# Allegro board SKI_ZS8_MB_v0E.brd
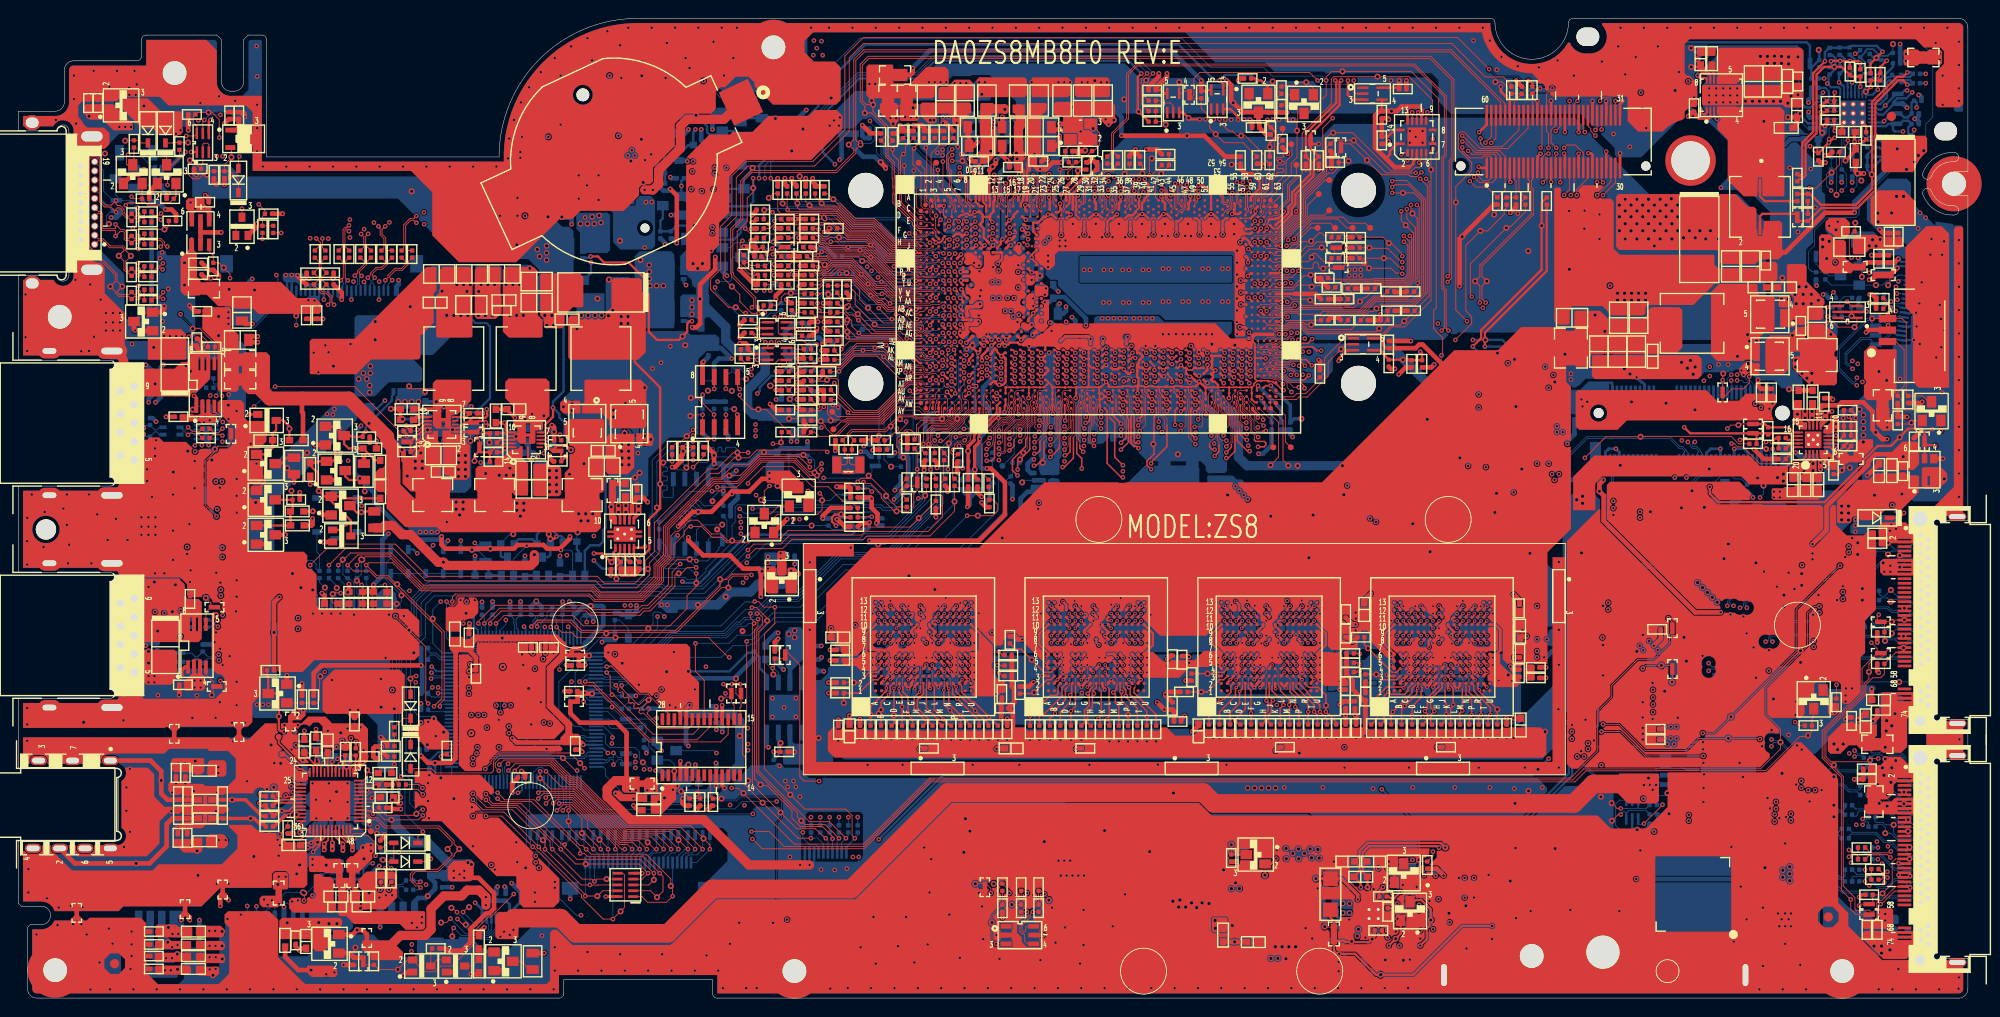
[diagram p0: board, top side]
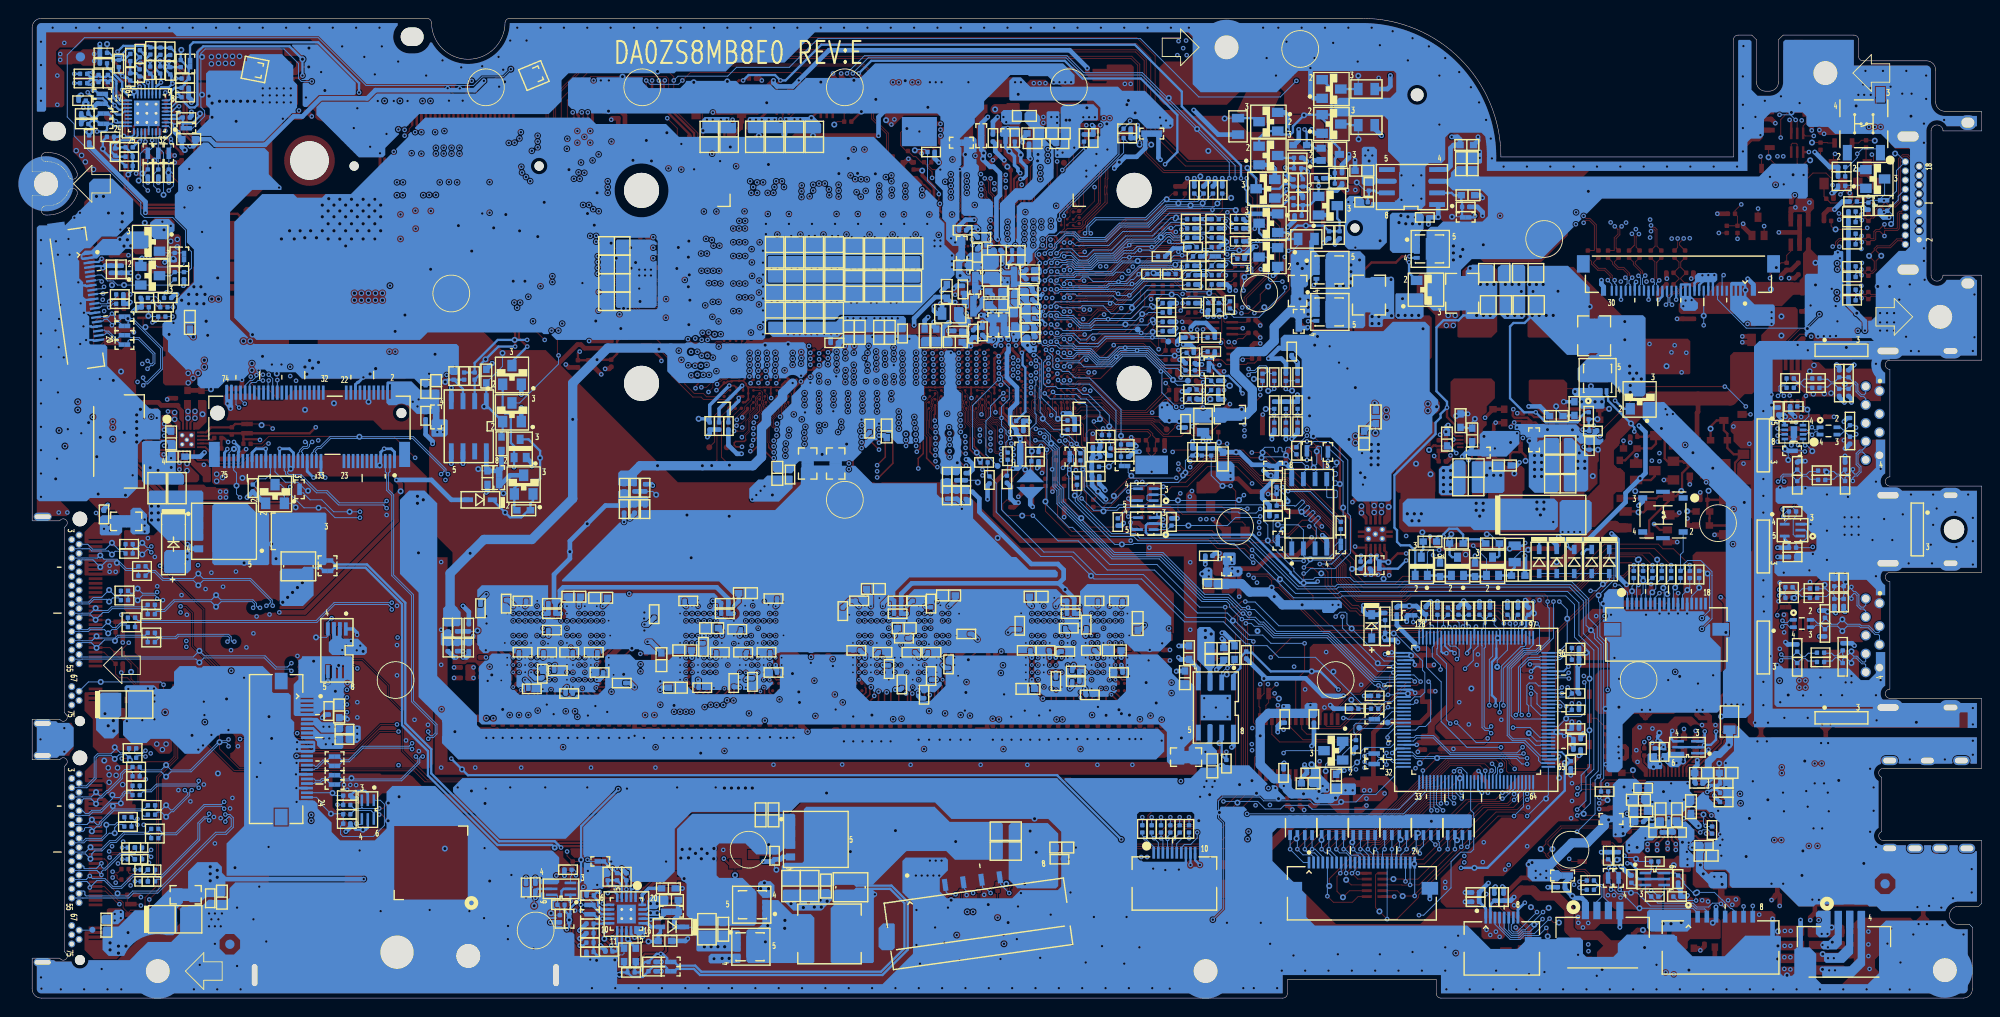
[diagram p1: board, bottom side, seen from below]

Outline 212.1 x 106.62 mm; copper layers: TOP, SGND, IN1, IN2, SVCC, IN3, SGND1, BOTTOM. Coordinates in mm from the lower left corner of the outline.
Outline path: 0,96.41 0,94.37 4.2,94.37 arc(4.85,95.02) 5.5,94.37 5.5,78.67 arc(4.85,78.02) 4.2,78.67 0,78.67 0,69.42 9.98,69.42 arc(10.48,68.92) 9.98,68.42 9.98,56.72 arc(10.48,56.22) 9.98,55.72 0,55.72 0,46.32 9.98,46.32 arc(10.48,45.82) 9.98,45.32 9.98,33.62 arc(10.48,33.12) 9.98,32.62 0,32.62 0,25 10.7,25 arc(11.19,24.6) 10.9,24.04 10.9,18.11 arc(11.19,17.55) 10.7,17.15 0,17.15 0,10.3 0.3,10 2.5,10 arc(3.5,9) 2.5,8 1.3,8 1,7.7 1,1 arc(1.29,0.29) 2,0 58.83,0 arc(59.18,0.15) 59.33,0.5 59.33,2 75.53,2 75.53,0.5 arc(75.68,0.15) 76.03,0 211.1,0 arc(211.81,0.29) 212.1,1 212.1,4.34 209.09,4.34 arc(208.42,4.23) 208.44,4.91 208.59,5.08 208.59,25.21 208.44,25.38 arc(208.43,26.05) 209.09,25.94 212.1,25.94 212.1,30.34 209.09,30.34 arc(208.42,30.23) 208.44,30.91 208.59,31.08 208.59,51.21 208.44,51.38 arc(208.42,52.05) 209.09,51.94 212.1,51.94 212.1,87.32 210.6,87.32 arc(209.3,88.62) 210.6,89.92 212.1,89.92 212.1,105.62 arc(211.81,106.33) 211.1,106.62 169.15,106.62 arc(168.8,106.48) 168.65,106.13 arc(164.65,102.17) 160.65,106.13 arc(160.5,106.48) 160.15,106.62 67.38,106.62 arc(56.72,102.2) 52.3,91.54 27,91.54 27,104.3 arc(26.85,104.65) 26.5,104.8 25,104.8 24.5,104.3 24.5,99.7 arc(24.21,98.99) 23.5,98.7 23.1,98.7 arc(22.39,98.99) 22.1,99.7 22.1,104.3 21.6,104.8 13.89,104.8 arc(13.54,104.65) 13.39,104.3 13.39,102.5 arc(13.25,102.15) 12.89,102 6,102 arc(5.29,101.71) 5,101 5,97.51 arc(4.71,96.8) 4,96.51 0.01,96.51 arc(0,96.46) 0,96.41 ; 207.21,89.79 arc(208.45,91.41) 210.4,92.02 210.6,92.02 arc(211.1,91.52) 210.6,91.02 210.4,91.02 arc(209.03,90.59) 208.15,89.45 arc(207.51,89.15) 207.21,89.79 ; 207.21,87.45 arc(207.51,88.09) 208.15,87.79 arc(209.03,86.65) 210.4,86.22 210.6,86.22 arc(211.1,85.72) 210.6,85.22 210.4,85.22 arc(208.45,85.83) 207.21,87.45

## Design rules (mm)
constraint set DEFAULT: min track width 0.102
net group W30-T123B: nets +3V3_ADO +5V_ADO_AVDD
net group W50-T123B: nets +5V_ADO_PVDD1 +5V_ADO_PVDD2
net group DFP-S4(4: nets CN_HDMI_CLKN CN_HDMI_CLKP CN_HDMI_TXN0 CN_HDMI_TXN1 CN_HDMI_TXN2 CN_HDMI_TXP0 CN_HDMI_TXP1 CN_HDMI_TXP2 EDP_AUXN EDP_AUXN_C EDP_AUXP EDP_AUXP_C EDP_TXN0 EDP_TXN0_C EDP_TXN1_C EDP_TXN2 EDP_TXN2_C EDP_TXN3 EDP_TXN3_C EDP_TXP0 EDP_TXP0_C EDP_TXP1_C EDP_TXP2 EDP_TXP2_C EDP_TXP3 EDP_TXP3_C HDMI_CLKN HDMI_CLKP HDMI_TXN0 HDMI_TXN1 HDMI_TXN2 HDMI_TXP0 HDMI_TXP1 HDMI_TXP2 PEG_RXN4 PEG_RXN5_L0 PEG_RXN5_L1 PEG_RXN5_L2 PEG_RXN5_L3 PEG_RXN6_L1 PEG_RXN6_L1_N PEG_RXN6_L2_N PEG_RXN6_L3 PEG_RXP4 PEG_RXP5_L0 PEG_RXP5_L1 PEG_RXP5_L2 PEG_RXP5_L3 PEG_RXP6_L1 PEG_RXP6_L1_N PEG_RXP6_L2_N PEG_RXP6_L3 PEG_TXN4 PEG_TXN5_L0 PEG_TXN5_L1 PEG_TXN5_L2 PEG_TXN5_L3 PEG_TXN6_L1 PEG_TXN6_L2_N PEG_TXN6_L3 PEG_TXP4 PEG_TXP5_L0 PEG_TXP5_L1 PEG_TXP5_L2 PEG_TXP5_L3 PEG_TXP6_L1 PEG_TXP6_L2_N PEG_TXP6_L3 R_PEG_TXN4 R_PEG_TXP4 SATA_RXN1/PEG_RXN6_L2 SATA_RXN3/PEG_RXN6_L0 SATA_RXP1/PEG_RXP6_L2 SATA_RXP3/PEG_RXP6_L0 SATA_TXN1/PEG_TXN6_L2 SATA_TXN3/PEG_TXN6_L0 SATA_TXP1/PEG_TXP6_L2 SATA_TXP3/PEG_TXP6_L0 USB2N0_R USB2N1 USB2N4 USB2N7 USB2P0_R USB2P1 USB2P4 USB2P7 USB3_RXN1 USB3_RXN1_USB3 USB3_RXN2 USB3_RXN2_USB3 USB3_RXP1 USB3_RXP1_USB3 USB3_RXP2 USB3_RXP2_USB3 USB3_TXN1 USB3_TXN1_R USB3_TXN1_USB3 USB3_TXN2 USB3_TXN2_R USB3_TXN2_USB3 USB3_TXP1 USB3_TXP1_R USB3_TXP1_USB3 USB3_TXP2 USB3_TXP2_R USB3_TXP2_USB3
net group DFP-S4W4-TB: nets PEG_RXN5_L1_N PEG_RXN5_L2_N PEG_RXN5_L3_N PEG_RXN6_L3_N PEG_RXP5_L1_N PEG_RXP5_L2_N PEG_RXP5_L3_N PEG_RXP6_L3_N PEG_TXN5_L1_N PEG_TXN5_L2_N PEG_TXN5_L3_N PEG_TXN6_L1_N PEG_TXN6_L3_N PEG_TXP5_L1_N PEG_TXP5_L2_N PEG_TXP5_L3_N PEG_TXP6_L1_N PEG_TXP6_L3_N SATA_RXN3/PEG_RXN6_L0_N SATA_RXP3/PEG_RXP6_L0_N SATA_TXN3/PEG_TXN6_L0_N SATA_TXP3/PEG_TXP6_L0_N USB2N3_C USB2N6_C USB2N7_C USB2P3_C USB2P6_C USB2P7_C
net group DFP-S5(5: nets CLK_PCIE_NGFF0_N CLK_PCIE_NGFF0_P CLK_PCIE_NGFF1_N CLK_PCIE_NGFF1_P CLK_PCIE_WLAN_N CLK_PCIE_WLAN_P CLK_PCIE_XDPN CLK_PCIE_XDPP
net group DFP-S5W4(4.5: nets 2ND_MBCLK 2ND_MBDATA CLK_SCLK CLK_SDATA DMIC_CLK DMIC_CLK_C DMIC_DATA DMIC_DATA_C HDMI_DDCCLK HDMI_DDCDAT MBCLK MBDATA PCH_I2C1_CLK PCH_I2C1_DAT SENSOR_PCH_CLK SENSOR_PCH_DAT SENSOR_SCL SENSOR_SDA SMB_ME1_CLK SMB_ME1_DAT SMB_PCH_CLK SMB_PCH_DAT TPCLK TPDATA
net group DFP-S5W4-TB: nets RTC_X1 RTC_X2 XTAL24_IN XTAL24_OUT
net group DFP-S7(5)W6.5(6)-T3: nets MA_CLKN0 MA_CLKN1 MA_CLKP0 MA_CLKP1 MA_DQSN1 MA_DQSN3 MA_DQSN5 MA_DQSN6 MA_DQSP1 MA_DQSP3 MA_DQSP5 MA_DQSP6 MB_CLKN0 MB_CLKN1 MB_CLKP0 MB_CLKP1 MB_DQSN1 MB_DQSN3 MB_DQSN5 MB_DQSN7 MB_DQSP1 MB_DQSP3 MB_DQSP5 MB_DQSP7
net group DFP-S7(7)W6.5(7.5)-T1: nets MB_DQSN0 MB_DQSN2 MB_DQSN4 MB_DQSN6 MB_DQSP0 MB_DQSP2 MB_DQSP4 MB_DQSP6
net group DFP-S7(7)W6.5(7.5)-T2: nets MA_DQSN0 MA_DQSN2 MA_DQSN4 MA_DQSN7 MA_DQSP0 MA_DQSP2 MA_DQSP4 MA_DQSP7
net group DFP-S15W40-T13B: nets L_SPK+ L_SPK- R_SPK+ R_SPK- SPK_L+ SPK_L- SPK_R+ SPK_R-
net group W4(4.5: nets 51624_ALERT# 51624_CLK 51624_DATA APWROK_R CLK_PCH_PCI3 CLK_PCH_PCI4 CLK_PCI_EC CLK_PCI_LPC CLK_PCI_LPC_C CLK_PCI_TPM DDR_PG_CTRL DNBSWON# DPWROK DPWROK_R DSWVREN EC_PWROK EC_PWROK_R H_CPU_SVIDART# H_CPU_SVIDCLK H_CPU_SVIDDAT H_PECI H_PROCHOT# H_PROCHOT#_R HDA_BCLK_R HDA_RST#_R HDA_SDO_R HDA_SYNC_R LPC_LAD0 LPC_LAD0_C LPC_LAD1 LPC_LAD1_C LPC_LAD2 LPC_LAD2_C LPC_LAD3 LPC_LAD3_C LPC_LFRAME# LPC_LFRAME#_C PCH_AZ_CODEC_BITCLK PCH_AZ_CODEC_RST# PCH_AZ_CODEC_SDIN0 PCH_AZ_CODEC_SDOUT PCH_AZ_CODEC_SYNC PCH_INTVRMEN PCH_PWRBTN# PCH_RSMRST# PCH_SPI_CLK PCH_SPI_CLK_EC PCH_SPI_CLK_R PCH_SPI_CS0# PCH_SPI_IO2 PCH_SPI_IO3 PCH_SPI_SI PCH_SPI_SI_EC PCH_SPI_SI_R PCH_SPI_SO PCH_SPI_SO_EC PCH_SPI_SO_R PCI_PLTRST# RSMRST# RTC_RST# SIO_EXT_SCI# SIO_EXT_SMI# SIO_RCIN# SM_INTRUDER# SPI_CS0#_UR_ME SPI_HOLD_IO3_ME SPI_WP_IO2_ME SRTC_RST# SYS_PWROK SYS_PWROK_R SYS_RESET# SYS_SHDN# THRMTRIP# VCCST_PWRGD VCCST_PWRGD_R VR_SVID_ALERT# VR_SVID_CLK VR_SVID_DATA XDP_BPM#0 XDP_BPM#1
net group W6.5(6)-T3: nets MA_DQ8 MA_DQ9 MA_DQ10 MA_DQ11 MA_DQ12 MA_DQ13 MA_DQ14 MA_DQ15 MA_DQ24 MA_DQ25 MA_DQ26 MA_DQ27 MA_DQ28 MA_DQ29 MA_DQ30 MA_DQ31 MA_DQ40 MA_DQ41 MA_DQ42 MA_DQ43 MA_DQ44 MA_DQ45 MA_DQ46 MA_DQ47 MA_DQ48 MA_DQ49 MA_DQ50 MA_DQ51 MA_DQ52 MA_DQ53 MA_DQ54 MA_DQ55 MB_DQ8 MB_DQ9 MB_DQ10 MB_DQ11 MB_DQ12 MB_DQ13 MB_DQ14 MB_DQ15 MB_DQ24 MB_DQ25 MB_DQ26 MB_DQ27 MB_DQ28 MB_DQ29 MB_DQ30 MB_DQ31 MB_DQ40 MB_DQ41 MB_DQ42 MB_DQ43 MB_DQ44 MB_DQ45 MB_DQ46 MB_DQ47 MB_DQ56 MB_DQ57 MB_DQ58 MB_DQ59 MB_DQ60 MB_DQ61 MB_DQ62 MB_DQ63
net group W6.5(7.5)-T1: nets MA_AMA0 MA_AMA1 MA_AMA2 MA_AMA3 MA_AMA4 MA_AMA5 MA_AMA6 MA_AMA7 MA_AMA8 MA_AMA9 MA_BMA0 MA_BMA1 MA_BMA2 MA_BMA3 MA_BMA4 MA_BMA5 MA_BMA6 MA_BMA7 MA_BMA8 MA_BMA9 MA_CKE0 MA_CKE1 MA_CKE2 MA_CKE3 MB_DQ0 MB_DQ1 MB_DQ2 MB_DQ3 MB_DQ4 MB_DQ5 MB_DQ6 MB_DQ7 MB_DQ16 MB_DQ17 MB_DQ18 MB_DQ19 MB_DQ20 MB_DQ21 MB_DQ22 MB_DQ23 MB_DQ32 MB_DQ33 MB_DQ34 MB_DQ35 MB_DQ36 MB_DQ37 MB_DQ38 MB_DQ39 MB_DQ48 MB_DQ49 MB_DQ50 MB_DQ51 MB_DQ52 MB_DQ53 MB_DQ54 MB_DQ55
net group W6.5(7.5)-T2: nets MA_DQ0 MA_DQ1 MA_DQ2 MA_DQ3 MA_DQ4 MA_DQ5 MA_DQ6 MA_DQ7 MA_DQ16 MA_DQ17 MA_DQ18 MA_DQ19 MA_DQ20 MA_DQ21 MA_DQ22 MA_DQ23 MA_DQ32 MA_DQ33 MA_DQ34 MA_DQ35 MA_DQ36 MA_DQ37 MA_DQ38 MA_DQ39 MA_DQ56 MA_DQ57 MA_DQ58 MA_DQ59 MA_DQ60 MA_DQ61 MA_DQ62 MA_DQ63 MB_AMA0 MB_AMA1 MB_AMA2 MB_AMA3 MB_AMA4 MB_AMA5 MB_AMA6 MB_AMA7 MB_AMA8 MB_AMA9 MB_BMA0 MB_BMA1 MB_BMA2 MB_BMA3 MB_BMA4 MB_BMA5 MB_BMA6 MB_BMA7 MB_BMA8 MB_BMA9 MB_CKE0 MB_CKE1 MB_CKE2 MB_CKE3
net group W6.5(7.5)-T12: nets MA_CS#0 MA_CS#1 MA_ODT MB_CS#0 MB_CS#1 MB_ODT
net group W6.5-TB: nets MA_AZQ0 MA_AZQ1 MA_BZQ0 MA_BZQ1 MB_AZQ0 MB_AZQ1 MB_BZQ0 MB_BZQ1
net group W10-T13B: nets USBCOMP
net group W10-T123B: nets 2.469V 3VPCU_AGND 5VPCU_AGND 670_CLK 670_EN 670_ENLDO 670PG 671_EN 671_FB 671PG 24737_ACDET 24737_ACN 24737_ACP 24737_BM# 24737_CMPIN 24737_CMPOUT 24737_ILIM 24737_SRN 24737_SRP 51211V_EN 51211V_FB 51211V_TRIP 51211V_TST 51216_MODE 51216_REF 51216_REFIN 51216_S3 51216_S5 51216_TRIP 51624_B-RAMP 51624_COMP 51624_CSN1 51624_CSN2 51624_CSP1 51624_CSP2 51624_DROOP 51624_F-IMAX 51624_GFB 51624_IMON 51624_MODE 51624_O-USR 51624_OCP-I 51624_PWM1 51624_PWM2 51624_SKIP# 51624_SLEWA 51624_THERM 51624_VBAT 51624_VFB 51624_VREF 51624_VRON +15V +VCCRTCEXT AGND_CPU AGND_DDR CS_BST1 CS_BSTR1 D/C# DDR_VTTT_PG_CTRL MAIND MODPHY_D S5D VCC_SENSE VL VRON VRON_CPU VSS_SENSE VSS_SENSE_R
net group W15-T13B: nets HP_IC_L HP_IC_R HP_L HP_R MIC2-VREFO
net group W15-T123B: nets 670_BST 670_BST1 671_BST 671_BST1 24737_BST 24737_REGN 24737_VCC 51211V_VBST 51216_VBST 51624_V5A +SM_VREF_CA OPI_COMP1 OPI_COMP2 PCIE_IREF PCIE_RCOMP SATA_IREF SATA_RCOMP
net group W15-TB: nets SM_RCOMP_0 SM_RCOMP_1 SM_RCOMP_2
net group W20-T13B: nets HPL_SYS HPR_SYS RING2
net group W20-T123B: nets 51624_VDD +1V5_ADO_AVDD2 +1V05_AUSB3PLL +1V05_CORE_PCH +1V05_DCPSUS4 +1V5_VCCATS +1V05_VCCST +1V05_VCCUSBCORE +1V05DX_MODPHY +3V3_EC +3V3_PCU_EC +3V3_PCU_ECAVCC +3V3_PCU_ECPLL +3V3_PCU_ECVBAT +3V3_RTC +3V3_S5_DEEP +3V3_S5_HDA +3V3_S5_PSPI +3V3_S5_SPI +3V3_TPM +3V3_VCCPTS +3V3_VCCSDIO +3V3_WLAN +3V_LDO +M_VREF_DQ1 +PCH_VCCDSW +SM_VREF_DQA +SM_VREF_DQB +TPVDD +VCCIOA_OUT +VCCPDSW CFG_RCOMP ECAGND TD_IREF
net group W20-TB: nets EDP_RCOMP
net group W40-T13B: nets RING2_R SLEEVE SLEEVE_R
net group W40-T123B: nets 24737_DH 24737_DL 51211V_DRVH 51211V_DRVL 51216_DRVH 51216_DRVL +1V05_AIDLE +1V05_APLLOPI +1V05_ASATA3PLL +1V05_AXCK_DCB +1V05_AXCK_LCPLL +1V05_DCPSUS1 +1V05_DCPSUS2 +1V05_DCPSUS3 +1V05_VCCASW +1V05_VCCASW_1 +1V05_VCCASW_2 +1V05_VCCCLK1 +1V05_VCCCLK2 +3V3_VCCPCORE +5V_FAN +DDR_VTT_RUN +M_VREF_CA +M_VREF_DQ0 +VCC_RTC +VCCIO_OUT VRTC1 VRTC2
net group W60-T123B: nets +3V3_SATA_N0 +3V3_SATA_N1 +5V_HDMI LCD_VCC LCD_VIN
net group W99-T123B: nets +5V_PCU_USB3_P0 +5V_S5_USB2 +5V_S5_USB3_P1

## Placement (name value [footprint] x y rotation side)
BT1  bat_conn  [BAT-AP-AAA-BAT-054-K01-2P-SMT]  64.79 91.05 25 top
C1  *0.1u/10v_4  [CC0402]  150.62 98.93 0 top
C2  0.1u/10v_4  [CC0402]  123.36 98.82 0 top
C3  *47u/6.3v_8  [CC0805]  115.79 97.67 270 top
C4  *47u/6.3v_8  [CC0805]  118.02 97.67 270 top
C5  47u/6.3v_8  [CC0805]  100.84 97.66 270 top
C6  47u/6.3v_8  [CC0805]  103 97.66 270 top
C7  0.1u/10v_4  [CC0402]  8.64 97.41 270 top
C8  47u/6.3v_8  [CC0805]  104.18 94.78 0 top
C9  47u/6.3v_8  [CC0805]  107.91 94.78 0 top
C10  47u/6.3v_8  [CC0805]  111.49 94.78 180 top
C11  0.1u/10v_4  [CC0402]  134.62 94.74 0 top
C12  *0.1u/10v_4  [CC0402]  148.34 93.34 90 top
C13  47u/6.3v_8  [CC0805]  104.33 92.75 0 top
C14  47u/6.3v_8  [CC0805]  107.91 92.75 0 top
C15  47u/6.3v_8  [CC0805]  111.49 92.75 180 top
C16  12p/50v_4  [CC0402]  114.29 92.19 180 top
C17  12p/50v_4  [CC0402]  116.42 92.19 0 top
C18  0.1u/10v_4  [CC0402]  118.48 91.2 90 top
C19  0.1u/10v_4  [CC0402]  119.62 91.2 90 top
C20  *0.1u/10v_4  [CC0402]  134.75 91.19 90 top
C21  1u/6.3v_4  [CC0402]  110.96 91.07 180 top
C22  1u/6.3v_4  [CC0402]  104.52 91.06 0 top
C23  1u/6.3v_4  [CC0402]  108.2 90.41 0 top
C24  0.1u/10v_4  [CC0402]  23.99 96.05 270 top
C25  1u/6.3v_4  [CC0402]  20.32 86.61 180 top
C26  0.1u/10v_4  [CC0402]  14.1 85.6 0 top
C27  *1000p/50v_4  [CC0402]  16.76 84.58 180 top
C28  0.1u/10v_4  [CC0402]  14.1 84.45 0 top
C29  0.1u/10v_4  [CC0402]  14.1 83.19 0 top
C30  0.1u/10v_4  [CC0402]  14.1 82.04 0 top
C31  0.1u/10v_4  [CC0402]  203.52 82.87 270 top
C32  1u/6.3v_4  [CC0402]  204.54 82.87 270 top
C33  0.1u/10v_4  [CC0402]  19.56 80.01 180 top
C34  0.1u/10v_4  [CC0402]  14.1 79.63 0 top
C35  0.1u/10v_4  [CC0402]  42.84 80.97 90 top
C36  0.1u/10v_4  [CC0402]  41.7 80.97 90 top
C37  0.1u/10v_4  [CC0402]  40.64 80.97 90 top
C38  0.1u/10v_4  [CC0402]  39.5 80.97 90 top
C39  0.1u/10v_4  [CC0402]  38.36 80.97 90 top
C40  0.1u/10v_4  [CC0402]  37.21 80.97 90 top
C41  0.1u/10v_4  [CC0402]  35.99 80.97 90 top
C42  0.1u/10v_4  [CC0402]  34.85 80.97 90 top
C43  0.1u/10v_4  [CC0402]  202.38 80.46 270 top
C44  1u/6.3v_4  [CC0402]  203.52 80.46 270 top
C45  2.2u/10v_4  [CC0402]  19.56 78.74 180 top
C46  0.1u/10v_4  [CC0402]  14.1 78.49 0 top
C47  *1u/6.3v_4  [CC0402]  90.11 77.16 90 top
C48  0.1u/10v_4  [CC0402]  14.1 77.09 0 top
C49  0.1u/10v_4  [CC0402]  202.38 79.31 90 bottom
C50  1u/6.3v_4  [CC0402]  203.52 79.31 90 bottom
C51  0.1u/10v_4  [CC0402]  14.1 75.95 0 top
C52  22u/6.3v_8  [CC0805]  24.32 74.62 90 top
C53  0.1u/10v_4  [CC0402]  32.26 80.97 90 top
C54  0.1u/10v_4  [CC0402]  33.4 80.97 90 top
C55  0.1u/10v_4  [CC0402]  31.31 74.31 90 top
C56  0.01u/25v_4  [CC0402]  32.5 74.31 90 top
C57  1000p/50v_4  [CC0402]  20.01 74.74 0 top
C58  0.1u/10v_4  [CC0402]  149.1 71.12 270 top
C59  4.7u/25v_8  [CC0805]  24.13 71.63 180 top
C60  150u/6.3v_3528  [CC3528]  17.02 68.96 270 top
C61  1000p/50v_4  [CC0402]  19.41 71.37 270 top
C62  0.1u/10v_4  [CC0402]  189.61 65.91 270 top
C63  0.1u/10v_4  [CC0402]  190.75 65.91 270 top
C64  1u/6.3v_4  [CC0402]  17.41 63.26 0 top
C65  15p/50v_4  [CC0402]  89.28 60.71 180 top
C66  15p/50v_4  [CC0402]  91.31 60.71 0 top
C67  1u/6.3v_4  [CC0402]  93.85 60.71 0 top
C68  *22p/50v_4  [CC0402]  72.26 59.56 90 top
C69  *10p/50v_4  [CC0402]  102.23 58.8 270 top
C70  *10p/50v_4  [CC0402]  100.84 56.13 90 top
C71  0.1u/10v_4  [CC0402]  90.93 54.48 0 top
C72  *18p/50v_4  [CC0402]  105.64 53.82 90 top
C73  *0.1u/10v_4  [CC0402]  90.93 51.31 0 top
C74  0.1u/10v_4  [CC0402]  202.25 50.61 0 top
C75  0.1u/10v_4  [CC0402]  202.25 49.47 0 top
C76  1000p/50v_4  [CC0402]  18.67 43.43 270 top
C77  1u/6.3v_4  [CC0402]  163.32 42.42 270 top
C78  10u/6.3v_6  [CC0603]  146.43 42.29 270 top
C79  1u/6.3v_4  [CC0402]  144.42 41.78 90 top
C80  1u/6.3v_4  [CC0402]  178.31 40.13 0 top
C81  10u/6.3v_6  [CC0603]  163.4 39.92 90 top
C82  1u/6.3v_4  [CC0402]  144.4 39.67 90 top
C83  0.1u/10v_4  [CC0402]  49.02 39.24 270 top
C84  10u/6.3v_6  [CC0603]  89.15 39.24 0 top
C85  150u/6.3v_3528  [CC3528]  16 38.23 90 top
C86  0.1u/10v_4  [CC0402]  55.44 38.17 0 top
C87  0.1u/10v_4  [CC0402]  57.72 38.17 180 top
C88  1u/6.3v_4  [CC0402]  89.41 37.89 0 top
C89  1u/6.3v_4  [CC0402]  163.37 37.46 90 top
C90  1u/6.3v_4  [CC0402]  125.56 36.88 270 top
C91  1u/6.3v_4  [CC0402]  126.62 36.83 270 top
C92  1u/6.3v_4  [CC0402]  89.41 36.75 0 top
C93  0.1u/10v_4  [CC0402]  60.58 36.2 0 top
C94  0.1u/10v_4  [CC0402]  165.1 35.99 180 top
C95  1u/6.3v_4  [CC0402]  163.32 35.35 270 top
C96  0.1u/10v_4  [CC0402]  49.78 35.31 90 top
C97  0.047u/25v_4  [CC0402]  165.1 34.84 180 top
C98  1u/6.3v_4  [CC0402]  144.4 33.96 90 top
C99  1u/6.3v_4  [CC0402]  17.9 34.1 0 top
C100  0.1u/10v_4  [CC0402]  60.45 33.4 0 top
C101  1u/6.3v_4  [CC0402]  107 33.09 90 top
C102  1u/6.3v_4  [CC0402]  146.55 32.81 270 top
C103  *1u/10v_4  [CC0402]  30.86 32.51 90 top
C104  0.047u/25v_4  [CC0402]  144.4 31.92 90 top
C105  0.1u/10v_4  [CC0402]  145.41 31.92 90 top
C106  0.047u/25v_4  [CC0402]  125.56 31.8 270 top
C107  1u/6.3v_4  [CC0402]  107.32 31.54 0 top
C108  1000p/50v_4  [CC0402]  36.58 30.1 90 top
C109  0.1u/10v_4  [CC0402]  126.11 30.1 180 top
C110  10u/6.3v_6  [CC0603]  163.45 29.72 270 top
C111  1u/6.3v_4  [CC0402]  144.4 29.39 270 top
C112  1u/6.3v_4  [CC0402]  145.54 29.39 270 top
C113  1u/6.3v_4  [CC0402]  161.92 29.38 270 top
C114  1u/6.3v_4  [CC0402]  178.12 29.28 0 top
C115  1u/6.3v_4  [CC0402]  91.57 29.26 270 top
C116  1u/6.3v_4  [CC0402]  107.58 29.26 270 top
C117  1u/6.3v_4  [CC0402]  89.21 29.21 270 top
C118  10u/6.3v_6  [CC0603]  90.42 29.08 270 top
C119  10u/6.3v_6  [CC0603]  128.4 29.08 270 top
C120  1u/6.3v_4  [CC0402]  178.12 28.13 0 top
C121  4.7u/6.3v_6  [CC0603]  31.12 27.43 270 top
C122  4.7u/6.3v_6  [CC0603]  32.38 27.66 270 top
C123  10u/6.3v_6  [CC0603]  33.66 27.43 270 top
C124  0.1u/10v_4  [CC0402]  60.58 27.43 90 top
C125  0.1u/10v_4  [CC0402]  137.8 27.3 0 top
C126  0.1u/10v_4  [CC0402]  155.32 27.3 0 top
C127  0.1u/10v_4  [CC0402]  99.06 27.18 0 top
C128  0.1u/10v_4  [CC0402]  116.08 27.18 0 top
C129  10u/6.3v_6  [CC0603]  108 27.18 0 top
C130  10u/6.3v_4  [CC0402]  46.61 26.92 270 top
C131  0.1u/10v_4  [CC0402]  201.11 23.82 0 top
C132  0.1u/10v_4  [CC0402]  201.11 24.96 0 top
C133  1000p/50v_4  [CC0402]  38.23 26.29 0 top
C134  100p/50v_4  [CC0402]  40.51 26.29 0 top
C135  *100p/50v_4  [CC0402]  18.16 24.51 90 top
C136  1u/16v_6  [CC0603]  39.88 24.51 180 top
C137  0.1u/10v_4  [CC0402]  199.46 30.17 270 top
C138  0.1u/10v_4  [CC0402]  54.74 24 0 top
C139  10u/6.3v_6  [CC0603]  200.98 30.17 270 top
C140  *100p/50v_4  [CC0402]  39.62 23.24 180 top
C141  100p/50v_4  [CC0402]  18.41 21.97 270 top
C142  10u/6.3v_6  [CC0603]  40.11 21.84 180 top
C143  *22p/50v_4  [CC0402]  39.62 20.7 180 top
C144  100p/50v_4  [CC0402]  18.41 19.94 270 top
C145  1u/10v_4  [CC0402]  29.3 18.29 90 top
C146  *100p/50v_4  [CC0402]  18.36 17.45 270 top
C147  10u/6.3v_6  [CC0603]  29.97 16.64 0 top
C148  *0.1u/10v_4  [CC0402]  202 14.04 180 top
C149  *0.1u/10v_4  [CC0402]  202 12.89 180 top
C150  0.1u/10v_4  [CC0402]  55.06 11.5 180 bottom
C151  10u/6.3v_6  [CC0603]  34.54 11.05 0 top
C152  10u/6.3v_6  [CC0603]  37.46 11.05 180 top
C153  1u/6.3v_4  [CC0402]  55.06 10.48 180 bottom
C154  0.1u/10v_4  [CC0402]  34.67 9.91 0 top
C155  0.1u/10v_4  [CC0402]  37.34 9.91 180 top
C156  0.1u/10v_4  [CC0402]  201.11 7.43 270 top
C157  0.1u/10v_4  [CC0402]  202.25 7.43 270 top
C158  *68p/50v_4  [CC0402]  14.73 7.24 0 top
C159  0.1u/10v_4  [CC0402]  52.01 10.99 270 bottom
C160  0.1u/10v_4  [CC0402]  30.17 6.29 90 top
C161  *68p/50v_4  [CC0402]  14.73 5.84 0 top
C162  1u/6.3v_4  [CC0402]  53.03 10.99 270 bottom
C163  *68p/50v_4  [CC0402]  14.73 4.57 0 top
C164  *68p/50v_4  [CC0402]  14.73 3.17 0 top
C165  10u/6.3v_6  [CC0603]  100.46 94.11 180 bottom
C166  10u/6.3v_6  [CC0603]  103.12 94.11 180 bottom
C167  *22u/6.3v_8  [CC0805]  127 93.73 270 bottom
C168  *22u/6.3v_8  [CC0805]  129.16 93.73 270 bottom
C169  22u/6.3v_8  [CC0805]  131.32 93.73 270 bottom
C170  22u/6.3v_8  [CC0805]  133.48 93.73 270 bottom
C171  22u/6.3v_8  [CC0805]  136.27 93.73 270 bottom
C172  22u/6.3v_8  [CC0805]  138.43 93.73 270 bottom
C173  1u/6.3v_4  [CC0402]  96.65 93.6 270 bottom
C174  1u/6.3v_4  [CC0402]  100.33 92.96 180 bottom
C175  1u/6.3v_4  [CC0402]  103.25 92.96 180 bottom
C176  0.1u/10v_4  [CC0402]  15.23 90.44 180 bottom
C177  *1000p/50v_4  [CC0402]  10.67 85.67 180 bottom
C178  1u/6.3v_4  [CC0402]  108.84 82.78 180 bottom
C179  1u/6.3v_4  [CC0402]  107.13 81.41 180 bottom
C180  1u/6.3v_4  [CC0402]  105.1 81.37 180 bottom
C181  22u/6.3v_8  [CC0805]  124.84 81.15 90 bottom
C182  22u/6.3v_8  [CC0805]  127 81.15 90 bottom
C183  22u/6.3v_8  [CC0805]  129.16 81.15 90 bottom
C184  22u/6.3v_8  [CC0805]  131.32 81.15 90 bottom
C185  22u/6.3v_8  [CC0805]  148.76 81.85 0 bottom
C186  22u/6.3v_8  [CC0805]  148.76 79.85 0 bottom
C187  1u/6.3v_4  [CC0402]  109.27 81.12 90 bottom
C188  22u/6.3v_8  [CC0805]  116.2 81.03 90 bottom
C189  22u/6.3v_8  [CC0805]  118.36 81.03 90 bottom
C190  22u/6.3v_8  [CC0805]  120.52 81.03 90 bottom
C191  22u/6.3v_8  [CC0805]  122.68 81.03 90 bottom
C192  1u/6.3v_4  [CC0402]  105.1 80.36 180 bottom
C193  1u/6.3v_4  [CC0402]  110.81 79.75 0 bottom
C194  1u/6.3v_4  [CC0402]  103.56 79.27 180 bottom
C195  22u/6.3v_8  [CC0805]  107.71 79.19 270 bottom
C196  1u/6.3v_4  [CC0402]  103.56 78.26 180 bottom
C197  22u/6.3v_8  [CC0805]  124.84 77.6 270 bottom
C198  22u/6.3v_8  [CC0805]  127 77.6 270 bottom
C199  22u/6.3v_8  [CC0805]  129.16 77.6 270 bottom
C200  22u/6.3v_8  [CC0805]  131.32 77.6 270 bottom
C201  *22u/6.3v_8  [CC0805]  116.35 77.47 270 bottom
C202  *22u/6.3v_8  [CC0805]  118.36 77.47 270 bottom
C203  22u/6.3v_8  [CC0805]  120.52 77.47 270 bottom
C204  22u/6.3v_8  [CC0805]  122.68 77.47 270 bottom
C205  1u/6.3v_4  [CC0402]  110.84 77.13 270 bottom
C206  0.1u/10v_4  [CC0402]  103.67 77.03 180 bottom
C207  *4.7u/6.3v_6  [CC0603]  112.59 76.9 270 bottom
C208  22u/6.3v_8  [CC0805]  148.76 75.83 0 bottom
C209  *22u/6.3v_8  [CC0805]  148.76 77.84 0 bottom
C210  1u/6.3v_4  [CC0402]  105.35 76.16 270 bottom
C211  1u/6.3v_4  [CC0402]  103.67 76.01 180 bottom
C212  1u/6.3v_4  [CC0402]  103.49 75 180 bottom
C213  22u/6.3v_8  [CC0805]  112.21 74.49 180 bottom
C214  22u/6.3v_8  [CC0805]  124.84 74.02 90 bottom
C215  22u/6.3v_8  [CC0805]  127 74.02 90 bottom
C216  *22u/6.3v_8  [CC0805]  129.16 74.02 90 bottom
C217  22u/6.3v_8  [CC0805]  131.32 74.02 90 bottom
C218  0.1u/10v_4  [CC0402]  103.49 73.98 180 bottom
C219  *10p/50v_4  [CC0402]  202.56 76.58 0 bottom
C220  1u/6.3v_4  [CC0402]  103.47 72.96 0 bottom
C221  1u/6.3v_4  [CC0402]  111.39 72.61 180 bottom
C222  1u/6.3v_4  [CC0402]  108.7 72.56 270 bottom
C223  10u/6.3v_6  [CC0603]  118.79 72.46 270 bottom
C224  10u/6.3v_6  [CC0603]  119.95 72.46 270 bottom
C225  10u/6.3v_6  [CC0603]  122.06 72.46 270 bottom
C226  10u/6.3v_6  [CC0603]  123.23 72.46 270 bottom
C227  2.2u/10v_4  [CC0402]  117.39 72.33 270 bottom
C228  1u/6.3v_4  [CC0402]  109.72 72.3 270 bottom
C229  *10p/50v_4  [CC0402]  202.56 75.56 0 bottom
C230  1u/6.3v_4  [CC0402]  103.47 71.95 0 bottom
C231  0.47u/25v_6  [CC0603]  111.66 71.37 180 bottom
C232  2.2u/10v_4  [CC0402]  124.83 71.31 180 bottom
C233  *0.1u/10v_4  [CC0402]  75.06 70.36 270 bottom
C234  *1.6p/50v_4  [CC0402]  15.49 67.94 270 bottom
C235  0.1u/10v_4  [CC0402]  20.83 67.44 0 bottom
C236  10u/6.3v_6  [CC0603]  168.15 66.55 270 bottom
C237  0.1u/10v_4  [CC0402]  20.83 66.42 0 bottom
C238  0.1u/10v_4  [CC0402]  169.29 66.29 270 bottom
C239  *1.6p/50v_4  [CC0402]  15.49 65.91 90 bottom
C240  0.1u/10v_4  [CC0402]  22.1 63.88 270 bottom
C241  0.1u/10v_4  [CC0402]  169.29 63.37 90 bottom
C242  22u/6.3v_8  [CC0805]  84.71 62.48 90 bottom
C243  1u/6.3v_4  [CC0402]  86.61 62.48 90 bottom
C244  2.2u/10v_4  [CC0402]  120.98 61.98 90 bottom
C245  0.1u/10v_4  [CC0402]  104.65 61.72 0 bottom
C246  10u/6.3v_6  [CC0603]  119.13 61.72 90 bottom
C247  0.1u/10v_4  [CC0402]  96.29 59.94 0 bottom
C248  *0.1u/10v_4  [CC0402]  84.84 59.44 90 bottom
C249  1u/6.3v_4  [CC0402]  103 59.44 0 bottom
C250  0.1u/10v_4  [CC0402]  96.29 58.93 0 bottom
C251  *1.6p/50v_4  [CC0402]  20.07 57.91 270 bottom
C252  10u/6.3v_6  [CC0603]  131.03 57.11 90 bottom
C253  2.2u/10v_4  [CC0402]  129.64 56.97 90 bottom
C254  0.1u/10v_4  [CC0402]  77.09 56.9 180 bottom
C255  1u/6.3v_4  [CC0402]  96.39 56.77 0 bottom
C256  0.022u/16v_4  [CC0402]  111.53 56.74 90 bottom
C257  *18p/50v_4  [CC0402]  106.05 56.46 90 bottom
C258  *18p/50v_4  [CC0402]  107.95 56.39 90 bottom
C259  *1.6p/50v_4  [CC0402]  20.07 55.88 90 bottom
C260  0.022u/16v_4  [CC0402]  146.54 55.53 90 bottom
C261  0.1u/10v_4  [CC0402]  111.53 54.71 90 bottom
C262  0.1u/10v_4  [CC0402]  147.7 53.21 90 bottom
C263  0.1u/10v_4  [CC0402]  204.28 52.64 270 bottom
C264  1u/6.3v_4  [CC0402]  84.07 48.13 180 bottom
C265  0.1u/10v_4  [CC0402]  20.57 48.01 0 bottom
C266  *0.1u/10v_4  [CC0402]  200.15 46.99 180 bottom
C267  *0.1u/10v_4  [CC0402]  200.15 45.97 180 bottom
C268  *1.6p/50v_4  [CC0402]  16.03 45.21 270 bottom
C269  0.1u/10v_4  [CC0402]  20.95 44.7 0 bottom
C270  10u/6.3v_6  [CC0603]  120.57 44.53 180 bottom
C271  10u/6.3v_6  [CC0603]  134.49 44.07 180 bottom
C272  10u/6.3v_6  [CC0603]  112.39 43.81 0 bottom
C273  10u/6.3v_6  [CC0603]  102.87 43.69 180 bottom
C274  10u/6.3v_6  [CC0603]  153.16 43.69 0 bottom
C275  0.1u/10v_4  [CC0402]  20.95 43.56 0 bottom
C276  10u/6.3v_6  [CC0603]  150.24 43.56 0 bottom
C277  1u/6.3v_4  [CC0402]  131.44 43.48 0 bottom
C278  1u/6.3v_4  [CC0402]  122.12 43.23 180 bottom
C279  1u/6.3v_4  [CC0402]  93.86 43.23 0 bottom
C280  1u/6.3v_4  [CC0402]  96.53 43.23 0 bottom
C281  0.1u/10v_4  [CC0402]  99.12 43.23 180 bottom
C282  1u/6.3v_4  [CC0402]  115.91 43.23 180 bottom
C283  0.047u/25v_4  [CC0402]  117.94 43.23 180 bottom
C284  1u/6.3v_4  [CC0402]  140.71 43.23 180 bottom
C285  1u/6.3v_4  [CC0402]  158.75 43.23 0 bottom
C286  *1.6p/50v_4  [CC0402]  16.03 43.05 90 bottom
C287  0.047u/25v_4  [CC0402]  136.75 42.97 180 bottom
C288  0.047u/25v_4  [CC0402]  155.55 42.97 180 bottom
C289  1u/6.3v_4  [CC0402]  114.3 42.93 90 bottom
C290  1u/6.3v_4  [CC0402]  160.53 42.93 270 bottom
C291  0.1u/10v_4  [CC0402]  199.14 42.8 180 bottom
C292  1u/6.3v_4  [CC0402]  163.32 42.42 270 bottom
C293  0.1u/10v_4  [CC0402]  60.45 42.16 90 bottom
C294  1u/6.3v_4  [CC0402]  123.9 42.11 270 bottom
C295  0.047u/25v_4  [CC0402]  99.12 41.83 180 bottom
C296  0.1u/10v_4  [CC0402]  117.94 41.83 180 bottom
C297  0.1u/10v_4  [CC0402]  136.75 41.83 180 bottom
C298  0.1u/10v_4  [CC0402]  155.55 41.83 180 bottom
C299  0.1u/10v_4  [CC0402]  199.14 41.78 180 bottom
C300  1u/6.3v_4  [CC0402]  144.42 41.78 90 bottom
C301  10u/6.3v_6  [CC0603]  91.82 40.77 90 bottom
C302  0.1u/10v_4  [CC0402]  97.41 40.64 90 bottom
C303  0.1u/10v_4  [CC0402]  104.65 40.51 90 bottom
C304  0.022u/16v_4  [CC0402]  165.86 40.31 90 bottom
C305  0.1u/10v_4  [CC0402]  99.31 40.26 180 bottom
C306  10u/6.3v_6  [CC0603]  117.22 40.26 180 bottom
C307  10u/6.3v_6  [CC0603]  138.18 40.26 0 bottom
C308  1u/6.3v_4  [CC0402]  135.38 40.13 0 bottom
C309  1u/6.3v_4  [CC0402]  155.55 40.05 180 bottom
C310  0.1u/10v_4  [CC0402]  199.14 39.75 180 bottom
C311  1u/6.3v_4  [CC0402]  110.46 39.62 0 bottom
C312  1u/6.3v_4  [CC0402]  64.9 39.37 90 bottom
C313  1u/6.3v_4  [CC0402]  117.25 39.17 0 bottom
C314  0.1u/10v_4  [CC0402]  199.14 38.73 180 bottom
C315  1u/6.3v_4  [CC0402]  139.06 38.23 270 bottom
C316  0.1u/10v_4  [CC0402]  164.59 38.15 90 bottom
C317  *1.6p/50v_4  [CC0402]  20.07 38.1 270 bottom
C318  10u/6.3v_6  [CC0603]  94.36 37.85 0 bottom
C319  1u/6.3v_4  [CC0402]  96.9 37.85 0 bottom
C320  1u/6.3v_4  [CC0402]  101.85 37.85 0 bottom
C321  1u/6.3v_4  [CC0402]  103.89 37.85 0 bottom
C322  1u/6.3v_4  [CC0402]  122.43 37.85 0 bottom
C323  10u/6.3v_6  [CC0603]  141.1 37.85 0 bottom
C324  1u/6.3v_4  [CC0402]  99.69 37.72 180 bottom
C325  1u/6.3v_4  [CC0402]  116.43 37.64 0 bottom
C326  1u/6.3v_4  [CC0402]  114.26 37.64 180 bottom
C327  1u/6.3v_4  [CC0402]  119.59 37.64 180 bottom
C328  1u/6.3v_4  [CC0402]  132.2 37.64 0 bottom
C329  1u/6.3v_4  [CC0402]  134.74 37.64 0 bottom
C330  1u/6.3v_4  [CC0402]  137.28 37.64 180 bottom
C331  1u/6.3v_4  [CC0402]  151 37.64 0 bottom
C332  1u/6.3v_4  [CC0402]  153.67 37.64 0 bottom
C333  1u/6.3v_4  [CC0402]  156.08 37.64 180 bottom
C334  1u/6.3v_4  [CC0402]  158.75 37.64 180 bottom
C335  10u/6.3v_6  [CC0603]  143.64 36.83 270 bottom
C336  1u/6.3v_4  [CC0402]  112.39 36.32 90 bottom
C337  *1.6p/50v_4  [CC0402]  20.07 36.07 90 bottom
C338  1u/6.3v_4  [CC0402]  118.87 35.81 270 bottom
C339  1u/6.3v_4  [CC0402]  154.91 35.64 180 bottom
C340  0.047u/25v_4  [CC0402]  98.56 35.61 180 bottom
C341  1u/6.3v_4  [CC0402]  93.85 35.43 0 bottom
C342  1u/6.3v_4  [CC0402]  131.44 35.43 0 bottom
C343  0.1u/10v_4  [CC0402]  150.37 35.43 0 bottom
C344  0.1u/10v_4  [CC0402]  156.59 35.31 90 bottom
C345  1u/6.3v_4  [CC0402]  114.3 35.05 90 bottom
C346  10u/6.3v_6  [CC0603]  86.68 34.86 270 bottom
C347  *150u/6.3v_3528  [CC3528]  201.87 31.94 0 bottom
C348  1u/6.3v_4  [CC0402]  100.71 34.49 270 bottom
C349  0.1u/10v_4  [CC0402]  98.56 34.46 180 bottom
C350  1u/6.3v_4  [CC0402]  133.73 34.42 270 bottom
C351  1u/6.3v_4  [CC0402]  135.76 34.29 90 bottom
C352  1u/6.3v_4  [CC0402]  147.95 34.29 0 bottom
C353  1u/6.3v_4  [CC0402]  117.48 34.14 90 bottom
C354  1u/6.3v_4  [CC0402]  139.19 33.78 180 bottom
C355  10u/6.3v_6  [CC0603]  142.11 33.78 180 bottom
C356  10u/6.3v_6  [CC0603]  103.76 33.66 0 bottom
C357  0.1u/10v_4  [CC0402]  157.73 33.66 180 bottom
C358  0.1u/10v_4  [CC0402]  153.67 33.15 180 bottom
C359  1u/6.3v_4  [CC0402]  115.06 33.02 90 bottom
C360  0.1u/10v_4  [CC0402]  97.03 32.99 180 bottom
C361  0.1u/10v_4  [CC0402]  66.04 32.89 180 bottom
C362  *10p/50v_4  [CC0402]  68.2 31.5 180 bottom
C363  10u/6.3v_6  [CC0603]  178.69 31.24 90 bottom
C364  0.1u/10v_4  [CC0402]  179.83 31.24 90 bottom
C365  0.1u/10v_4  [CC0402]  202.63 31.31 0 top
C366  tpm@0.1u/10v_4  [CC0402]  72.64 30.35 90 bottom
C367  tpm@0.1u/10v_4  [CC0402]  75.82 30.35 90 bottom
C368  10u/6.3v_6  [CC0603]  202.38 32.45 0 top
C369  0.1u/10v_4  [CC0402]  178.12 29.28 0 bottom
C370  0.1u/10v_4  [CC0402]  44.02 28.19 0 bottom
C371  0.1u/10v_4  [CC0402]  178.12 28.13 0 bottom
C372  *0.1u/10v_4  [CC0402]  200.79 25.15 180 bottom
C373  10u/6.3v_6  [CC0603]  27.81 24.51 0 bottom
C374  10u/6.3v_6  [CC0603]  30.48 24.51 180 bottom
C375  tpm@0.1u/10v_4  [CC0402]  73.02 24.51 180 bottom
C376  tpm@0.1u/10v_4  [CC0402]  75.95 24.51 270 bottom
C377  *0.1u/10v_4  [CC0402]  200.79 24.13 180 bottom
C378  tpm@10u/6.3v_6  [CC0603]  70.23 23.62 270 bottom
C379  0.1u/10v_4  [CC0402]  30.73 23.37 180 bottom
C380  tpm@10u/6.3v_6  [CC0603]  73.28 23.37 180 bottom
C381  0.1u/10v_4  [CC0402]  36.83 22.86 0 bottom
C382  2.2u/10v_4  [CC0402]  28.07 22.35 0 bottom
C383  10u/6.3v_6  [CC0603]  37.34 21.59 0 bottom
C384  *0.1u/10v_4  [CC0402]  199.11 20.98 180 bottom
C385  10u/6.3v_6  [CC0603]  31.62 20.83 270 bottom
C386  10u/6.3v_6  [CC0603]  37.08 20.32 0 bottom
C387  *0.1u/10v_4  [CC0402]  199.11 19.96 180 bottom
C388  10u/6.3v_6  [CC0603]  33.15 19.94 270 bottom
C389  10u/6.3v_6  [CC0603]  34.92 19.94 270 bottom
C390  0.1u/10v_4  [CC0402]  37.21 19.18 0 bottom
C391  *0.1u/10v_4  [CC0402]  198.75 18.41 180 bottom
C392  1u/10v_4  [CC0402]  29.34 18.29 90 bottom
C393  0.1u/10v_4  [CC0402]  33.15 18.03 180 bottom
C394  0.1u/10v_4  [CC0402]  35.18 18.03 0 bottom
C395  *0.1u/10v_4  [CC0402]  198.75 17.4 180 bottom
C396  0.1u/10v_4  [CC0402]  30.23 16.64 0 bottom
C397  0.01u/16v_4  [CC0402]  200.53 16.38 180 bottom
C398  10u/6.3v_6  [CC0603]  29.97 15.49 0 bottom
C399  0.01u/16v_4  [CC0402]  200.53 15.11 180 bottom
C400  *0.1u/10v_4  [CC0402]  199.12 13.97 180 bottom
C401  0.01u/16v_4  [CC0402]  199.9 13.97 0 bottom
C402  *0.1u/10v_4  [CC0402]  199.12 12.7 180 bottom
C403  0.01u/16v_4  [CC0402]  199.9 12.7 0 bottom
C404  0.1u/10v_4  [CC0402]  45.72 12.06 180 bottom
C405  10u/6.3v_6  [CC0603]  191.46 10.99 90 bottom
C406  0.1u/10v_4  [CC0402]  192.73 10.86 90 bottom
C407  *0.1u/10v_4  [CC0402]  39.44 13.02 270 top
C408  *0.1u/10v_4  [CC0402]  40.58 13.02 270 top
C409  *150u/6.3v_3528  [CC3528]  196.54 8.58 0 bottom
C410  10u/6.3v_6  [CC0603]  204.03 7.94 270 bottom
C712  0.22u/25v_6  [CC0603]  31.31 6.16 90 top
C713  *1000p/50v_4  [CC0402]  36.52 4 90 top
C714  *1000p/50v_4  [CC0402]  196.6 80.71 90 bottom
CLIP1  sul-12a2m  [EMIPAD47X31-63X24-3P]  86.1 43.75 270 top
CLIP2  sul-12a2m  [EMIPAD47X31-63X24-3P]  167.6 43.75 270 top
CLIP3  *sul-12a2m  [EMIPAD47X31-63X24-3P]  100 25 0 top
CLIP4  *sul-12a2m  [EMIPAD47X31-63X24-3P]  127.65 25 0 top
CLIP5  *sul-12a2m  [EMIPAD47X31-63X24-3P]  155 25 0 top
CLIP6  sul-12a2m  [EMIPAD47X31-63X24-3P]  15.25 70.5 180 bottom
CLIP7  sul-12a2m  [EMIPAD47X31-63X24-3P]  23.75 60.15 270 bottom
CLIP8  *sul-12a2m  [EMIPAD47X31-63X24-3P]  7 51 270 bottom
CLIP9  *sul-12a2m  [EMIPAD47X31-63X24-3P]  23.75 49.15 270 bottom
CLIP10  sul-12a2m  [EMIPAD47X31-63X24-3P]  23.75 38.15 270 bottom
CLIP11  *sul-12a2m  [EMIPAD47X31-63X24-3P]  15.25 30.5 180 bottom
CLIP12  emipad63x56  [EMIPAD63X56]  188.29 101.15 10.9 bottom
CLIP13  emipad63x56  [EMIPAD63X56]  157.93 100.22 337.5 bottom
CN1  *xdp  [BSH-030-01-L-D-A-TR-60P-LDH]  167 93.22 0 top
CN2  hdmi  [HDMI-C128F4-K1909-L-19P-SMT]  1.5 86.52 270 top
CN3  fan  [1775295-4-4P-L]  206.85 72.08 90 top
CN4  usb3.0 conn  [USB-53063-00902-001-9P-SMT]  3.38 62.57 270 top
CN5  usb3.0 conn  [USB-53063-00902-001-9P-SMT]  3.38 39.47 270 top
CN6  tsh-5746dt1r2-h3-105-g6  [PHJK-2SJ3095-033111F-6P]  2.99 21 270 top
CN7  sensor db  [LVDS-50473-0200M-001-20P-L]  208.35 75.91 262 bottom
CN8  edp  [LVDS-50473-0300M-V01-30P-L]  32.98 79.9 0 bottom
CN9  wlan_ngff conn(type 2230)  [MINIPCI-SM3ZS067U215AE-75P-KE]  181.93 63.67 0 bottom
CN10  ngff_ssd  [NGFF-80159-2181-75P-KM]  206.9 41.14 90 top
CN11  *aps  [88511-180N-18P-L]  34.29 40.13 180 bottom
CN12  usb db  [50501-02401-001-24P-L]  185 27.1 270 bottom
CN13  ngff_ssd  [NGFF-80159-2181-75P-KM]  206.9 15.14 90 top
CN14  *debug  [88511-10XX-10P-L]  87.82 13.02 180 bottom
CN15  tp  [88513-0801-8P-L]  28.4 8.86 180 bottom
CN16  kb  [50501-02401-001-24P-L]  67.43 11.95 180 bottom
CN17  dmic  [1775295-4-4P-L]  41.23 6.03 180 bottom
CN18  led db  [50501-0080N-001-8P-L]  52.2 5.96 180 bottom
CN19  speaker  [1775295-4-4P-L]  14.97 5.03 180 bottom
CP1  *100p/50vx4  [8P4R]  56.9 18.54 0 bottom
CP2  *100p/50vx4  [8P4R]  60.33 18.54 0 bottom
CP3  *100p/50vx4  [8P4R]  63.75 18.54 0 bottom
CP4  *100p/50vx4  [8P4R]  67.18 18.54 0 bottom
CP5  *100p/50vx4  [8P4R]  70.61 18.54 0 bottom
CP6  *100p/50vx4  [8P4R]  74.04 18.54 0 bottom
D1  *14v/100p_4  [CC0402]  7.62 97.41 270 top
D2  rb500v-40  [DSM]  14.1 94.36 90 top
D3  rb500v-40  [DSM]  16 94.36 90 top
D4  rb500v-40  [DSM]  23.94 88.97 90 top
D5  *0.2pf/5v_4  [RC0402]  22.42 89.6 270 top
D6  *0.2pf/5v_4  [RC0402]  22.98 96.05 270 top
D7  bat54c  [SOT23_213-3_3-2]  83.06 45.72 270 top
D8  rb500v-40  [DSM]  42.67 31.75 90 top
D9  rb500v-40  [DSM]  42.67 26.29 270 top
D10  *14v/38v/100p_4  [CC0402]  17.14 24.51 90 top
D11  *14v/38v/100p_4  [CC0402]  17.4 21.97 270 top
D12  *14v/38v/100p_4  [CC0402]  17.4 19.94 270 top
D13  *14v/38v/100p_4  [CC0402]  17.35 17.45 270 top
D14  rb500v-40  [DSM]  42.16 16.89 180 top
D15  rb500v-40  [DSM]  42.16 14.86 180 top
D16  *14v/100p_4  [CC0402]  15.23 89.42 180 bottom
D17  *0.2pf/5v_4  [RC0402]  12.32 86.18 90 bottom
D18  *0.2pf/5v_4  [RC0402]  14.48 67.94 270 bottom
D19  *0.2pf/5v_4  [RC0402]  14.48 65.91 90 bottom
D20  *0.2pf/5v_4  [RC0402]  14.33 62.74 270 bottom
D21  *0.2pf/5v_4  [RC0402]  14.33 60.71 90 bottom
D22  *0.2pf/5v_4  [RC0402]  14.86 57.91 270 bottom
D23  *0.2pf/5v_4  [RC0402]  14.86 55.88 90 bottom
D24  rb500v-40  [DSM]  40.51 47.52 270 bottom
D25  *rb500v-40  [DSM]  42.42 47.52 270 bottom
D26  rb500v-40  [DSM]  44.32 47.52 270 bottom
D27  *rb500v-40  [DSM]  46.23 47.52 270 bottom
D28  rb500v-40  [DSM]  48.13 47.52 270 bottom
D29  *0.2pf/5v_4  [RC0402]  15.01 45.21 270 bottom
D30  *0.2pf/5v_4  [RC0402]  15.01 43.05 90 bottom
D31  *0.2pf/5v_4  [RC0402]  17.04 39.75 90 bottom
D32  sdmk0340l-7-f  [DSMV]  66.36 40.45 270 bottom
D33  *0.2pf/5v_4  [RC0402]  17.04 41.78 270 bottom
D34  *0.2pf/5v_4  [RC0402]  15.11 38.23 270 bottom
D35  *0.2pf/5v_4  [RC0402]  15.11 36.07 90 bottom
HE1  em-6781-t3  [SOT23_123-2_8-1_9]  24.51 93.51 180 top
HOLE1  *h-c236d102p2  [H-C236D102P2]  82.15 103.47 0 top
HOLE2  *h-tc236bc197d102p2  [H-TC236BC197D102P2]  17 100.67 0 top
HOLE3  *h-o98x79d98x79n  [H-O98X79D98X79N]  170.75 104.62 0 top
HOLE4  mbzs8001010  [H-TC217BC165D165P2]  181.93 91.15 0 top
HOLE5  *h-c236d102p2  [H-C236D102P2]  210.6 88.62 0 top
HOLE6  *h-c150d150n  [H-C150D150N]  92.2 87.9 0 top
HOLE7  *h-c150d150n  [H-C150D150N]  145.8 87.9 0 top
HOLE8  *h-c236d102p2  [H-C236D102P2]  4.5 74.14 0 top
HOLE9  *h-c150d150n  [H-C150D150N]  92.2 66.9 0 top
HOLE10  *h-c150d150n  [H-C150D150N]  145.8 66.9 0 top
HOLE11  *h-c236d102p2  [O-SKI-1]  164.65 4.58 0 top
HOLE12  *h-c236d102p2  [H-C236D102P2]  4 3.04 0 top
HOLE13  *h-c236d102p2  [H-C236D102P2]  84.43 2.94 0 top
HOLE14  *h-c236d102p2  [H-C236D102P2]  198.43 2.94 0 top
HOLE15  fbaj2003010  [H-C217D142P2]  172.4 5 0 top
HOLE16  *h-c87d87n  [H-C87D87N]  3 51 0 top
HOLE18  *h-o98x79d98x79n  [H-O98X79D98X79N]  209.68 94.35 0 top
J2  *jump  [SOLDERJUMPER-2]  103.5 55.88 270 bottom
JP2  *short_3720  [SHORT3720]  168.91 70.74 270 top
JP3  *short_3720  [SHORT3720]  195.71 69.98 0 top
JP4  *short_3720  [SHORT3720]  45.08 54.74 0 top
JP5  *short_3720  [SHORT3720]  51.82 54.74 0 top
JP6  *short_3720  [SHORT3720]  61.34 54.74 0 top
JP7  *short_3720  [SHORT3720]  42.15 72.08 90 bottom
JP8  *short_3720  [SHORT3720]  56.52 76.71 270 bottom
JP9  *short_3720  [SHORT3720]  66.65 76.5 270 bottom
L1  2.2uh/210ma_8  [RC0805]  105.37 97.67 90 top
L2  2.2uh/210ma_8  [RC0805]  108.83 97.67 90 top
L3  2.2uh/210ma_8  [RC0805]  111.06 97.67 90 top
L4  2.2uh/210ma_8  [RC0805]  113.55 97.67 90 top
L5  2.2uh/210ma_8  [RC0805]  98.81 97.66 90 top
L6  0_6  [RC0603]  20.22 24.74 0 top
L7  0_6  [RC0603]  20.32 21.59 0 top
L8  0_6  [RC0603]  20.32 19.56 0 top
L9  0_6  [RC0603]  20.27 17.07 0 top
L11  mcm2012b900gbe/0.4a/90  [FILTER-MCM2012B900GBE-4P]  16.66 61.72 180 bottom
L14  120_0.5a_4  [RC0402]  63.63 42.14 90 bottom
L15  mcm2012b900gbe/0.4a/90  [FILTER-MCM2012B900GBE-4P]  19.56 40.77 180 bottom
L17  22_6a_8  [RC0805]  27.43 30.1 90 bottom
L18  120_0.5a_4  [RC0402]  44.2 29.34 0 bottom
L19  120_0.5a_4  [RC0402]  44.02 27.05 180 bottom
NOREF  -  []  0 -50.8 0 top
NOREF#2  -  []  182.18 11.29 0 top
NOREF#3  -  [unnamed#2]  196.92 8.83 0 top
NOREF#4  -  [unnamed#2]  10.48 3.75 0 top
NOREF#5  -  []  159.07 -35.24 0 top
NOREF#6  -  [unnamed#2]  203.77 95.95 0 top
NOREF#7  -  []  168.71 14.72 180 bottom
NOREF#8  -  [unnamed#2]  206.85 102.43 180 bottom
NOREF#9  -  [unnamed#2]  190.59 5.86 180 bottom
NOREF#10  -  [unnamed#2]  10.51 12.44 180 bottom
PC1  4.7u/25v_8  [CC0805]  190.82 99.76 270 top
PC2  1n/50v_4  [CC0402]  199.26 100.84 270 top
PC3  4.7u/25v_8  [CC0805]  188.79 99.76 270 top
PC4  0.22u/25v_6  [CC0603]  183.01 102.23 270 top
PC5  0.1u/50v_6  [CC0603]  192.47 99.76 270 top
PC6  2200p/50v_4  [CC0402]  193.61 99.76 270 top
PC7  1u/6.3v_4  [CC0402]  197.17 95.57 180 top
PC8  2.2u/10v_6  [CC0603]  199.14 94.26 0 top
PC9  0.33u/6.3v_4  [CC0402]  201.04 93.85 270 top
PC10  1000p/50v_6  [CC0603]  193.52 96.6 270 top
PC11  0.1u/10v_4  [CC0402]  195.83 91.57 270 top
PC12  1u/10v_4  [CC0402]  182.31 96.84 270 top
PC13  15u/25v_7343  [CC7343]  204.22 88.77 270 top
PC14  *330u/2v_7343  [CC7343]  182.88 82.55 270 top
PC15  0.1u/10v_4  [CC0402]  190.12 80.26 90 top
PC16  22u/6.3v_8  [CC0805]  186.31 79.63 90 top
PC17  22u/6.3v_8  [CC0805]  188.47 79.63 90 top
PC18  22u/6.3v_8  [CC0805]  45.79 78.81 180 top
PC19  *22u/6.3v_8  [CC0805]  49.34 78.81 0 top
PC20  22u/6.3v_8  [CC0805]  52.9 78.81 180 top
PC21  *22u/6.3v_8  [CC0805]  56.39 77.98 0 top
PC22  *680p/50v_6  [CC0603]  192.15 77.34 180 top
PC23  330u/2v_7343  [CC7343]  63.37 76.8 180 top
PC24  0.1u/50v_6  [CC0603]  52.83 75.95 180 top
PC25  0.1u/50v_6  [CC0603]  45.34 75.69 180 top
PC26  22u/6.3v_8  [CC0805]  56.39 75.69 0 top
PC27  22u/6.3v_8  [CC0805]  49.28 75.44 0 top
PC28  *0.1u/16v_4  [CC0402]  52.58 74.85 180 top
PC29  *22u/6.3v_8  [CC0805]  169.04 74.04 180 top
PC30  22u/6.3v_8  [CC0805]  174.12 74.04 90 top
PC31  22u/6.3v_8  [CC0805]  176.28 74.04 90 top
PC32  0.1u/50v_6  [CC0603]  59.69 73.86 180 top
PC33  4.7u/25v_8  [CC0805]  195.71 73.53 270 top
PC34  2200p/50v_4  [CC0402]  193.93 73.15 90 top
PC35  *22u/6.3v_8  [CC0805]  171.96 70.36 270 top
PC36  22u/6.3v_8  [CC0805]  173.99 70.36 270 top
PC37  22u/6.3v_8  [CC0805]  176.02 70.36 270 top
PC38  0.1u/50v_6  [CC0603]  177.8 69.85 270 top
PC39  0.1u/50v_6  [CC0603]  195.2 65.41 90 top
PC40  1u/10v_4  [CC0402]  196.47 64.9 90 top
PC41  0.1u/50v_6  [CC0603]  42.29 64.11 180 top
PC42  0.1u/50v_6  [CC0603]  53.9 64.08 180 top
PC43  0.1u/16v_4  [CC0402]  49.5 63.65 0 top
PC44  1u/6.3v_4  [CC0402]  42.29 61.72 180 top
PC45  1u/6.3v_4  [CC0402]  51.69 61.47 180 top
PC46  0.01u/25v_4  [CC0402]  199.01 61.21 180 top
PC47  *2.2n/50v_4  [CC0402]  37.85 61.09 0 top
PC48  0.1u/10v_4  [CC0402]  199.01 60.07 180 top
PC49  2200p/50v_6  [CC0603]  63.63 59.56 0 top
PC50  *0.1u/10v_4  [CC0402]  51.69 59.41 0 top
PC51  4.7u/25v_8  [CC0805]  45.97 59.05 180 top
PC52  4.7u/25v_8  [CC0805]  63.75 57.78 180 top
PC53  4.7u/25v_8  [CC0805]  55.83 57.43 180 top
PC54  0.22u/10v_4  [CC0402]  197.49 57.4 90 top
PC55  0.1u/50v_6  [CC0603]  202.44 57.4 90 top
PC56  0.1u/50v_6  [CC0603]  203.83 57.4 270 top
PC57  2200p/50v_6  [CC0603]  46.23 57.28 0 top
PC58  10u/6.3v_6  [CC0603]  193.04 55.88 270 top
PC59  10u/6.3v_6  [CC0603]  194.44 55.88 90 top
PC60  10u/6.3v_6  [CC0603]  195.83 55.88 90 top
PC61  4.7u/25v_8  [CC0805]  55.85 55.42 180 top
PC62  0.1u/50v_6  [CC0603]  66.04 55.25 90 top
PC63  1u/10v_4  [CC0402]  67.31 54.86 90 top
PC64  *2.2n/50v_4  [CC0402]  30.23 54.23 0 top
PC65  0.1u/50v_6  [CC0603]  144.65 14.86 0 top
PC66  0.1u/50v_6  [CC0603]  147.45 14.86 0 top
PC67  0.1u/50v_6  [CC0603]  146.05 13.21 0 top
PC68  *47p/50v_4  [CC0402]  109.09 12.06 270 top
PC69  *47p/50v_4  [CC0402]  111 12.06 270 top
PC70  *680p/50v_6  [CC0603]  134.37 6.1 180 top
PC71  1000p/50v_4  [CC0402]  202.67 101.7 270 bottom
PC72  *0.1u/25v_4  [CC0402]  206.5 100.58 180 bottom
PC73  0.12u/10v_4  [CC0402]  203.86 100.08 90 bottom
PC74  *0.1u/25v_4  [CC0402]  206.5 99.57 180 bottom
PC75  *0.01u/50v_4  [CC0402]  206.38 96.27 180 bottom
PC76  *330p/50v_4  [CC0402]  206.38 95.12 180 bottom
PC77  1500p/50v_4  [CC0402]  203.58 93.73 180 bottom
PC78  1u/16v_6  [CC0603]  56.01 92.84 180 bottom
PC79  *100p/50v_4  [CC0402]  203.07 92.08 270 bottom
PC80  *2200p/50v_4  [CC0402]  74.42 91.44 180 bottom
PC81  0.1u/50v_6  [CC0603]  55.37 90.8 90 bottom
PC82  10u/6.3v_6  [CC0603]  56.64 90.8 270 bottom
PC83  10u/6.3v_6  [CC0603]  67.44 90.04 180 bottom
PC84  *1u/10v_4  [CC0402]  72.02 89.22 180 bottom
PC85  *2.2n/50v_4  [CC0402]  74.87 88.71 90 bottom
PC86  *0.1u/50v_6  [CC0603]  55.88 87.38 180 bottom
PC87  22u/6.3v_8  [CC0805]  49.34 78.93 0 bottom
PC88  22u/6.3v_8  [CC0805]  53.03 78.93 180 bottom
PC89  22u/6.3v_8  [CC0805]  49.28 75.44 0 bottom
PC90  22u/6.3v_8  [CC0805]  52.83 75.44 180 bottom
PC91  0.1u/50v_6  [CC0603]  194.94 73.53 270 bottom
PC92  0.1u/50v_6  [CC0603]  162.69 67.69 90 bottom
PC93  *680p/50v_6  [CC0603]  46.28 63.35 180 bottom
PC94  *680p/50v_6  [CC0603]  55.42 61.29 90 bottom
PC95  *680p/50v_6  [CC0603]  67.18 60.96 90 bottom
PC96  0.1u/50v_6  [CC0603]  196.98 60.96 90 bottom
PC97  10u/6.3v_6  [CC0603]  58.17 60.83 270 bottom
PC98  4.7u/25v_8  [CC0805]  45.85 60.2 180 bottom
PC99  *0.1u/10v_4  [CC0402]  42.67 60.07 90 bottom
PC100  2200p/50v_6  [CC0603]  196.21 58.93 180 bottom
PC101  4.7u/25v_8  [CC0805]  45.85 58.09 180 bottom
PC102  2200p/50v_6  [CC0603]  51.92 57.96 180 bottom
PC103  4.7u/25v_8  [CC0805]  55.83 57.68 180 bottom
PC104  0.1u/50v_6  [CC0603]  162.56 56.64 270 bottom
PC105  4.7u/25v_8  [CC0805]  45.85 55.98 180 bottom
PC106  4.7u/25v_8  [CC0805]  55.85 55.68 180 bottom
PC107  15u/25v_7343  [CC7343]  47.75 52.58 180 bottom
PC108  0.1u/50v_6  [CC0603]  53.21 49.48 180 bottom
PC109  0.1u/50v_6  [CC0603]  57.15 49.48 0 bottom
PC110  0.1u/50v_6  [CC0603]  60.02 49.68 0 bottom
PC111  0.1u/50v_6  [CC0603]  55.12 46.61 90 bottom
PC112  0.1u/50v_6  [CC0603]  58.93 46.61 90 bottom
PC113  0.1u/50v_6  [CC0603]  50.42 45.97 180 bottom
PC114  10u/6.3v_6  [CC0603]  83.19 38.1 0 bottom
PC115  *0.1u/50v_6  [CC0603]  81.28 37.59 90 bottom
PC116  1u/16v_6  [CC0603]  86.23 37.59 90 bottom
PC117  0.1u/50v_6  [CC0603]  83.19 36.83 180 bottom
PC118  10u/6.3v_6  [CC0603]  83.69 25.27 90 bottom
PC119  0.1u/50v_6  [CC0603]  131.44 19.94 270 bottom
PC120  2200p/50v_6  [CC0603]  132.84 19.94 90 bottom
PC121  0.1u/50v_6  [CC0603]  100.08 16.38 0 bottom
PC122  *100p/50v_4  [CC0402]  100.33 15.11 180 bottom
PC123  2200p/50v_6  [CC0603]  125.73 12.19 270 bottom
PC124  10u/25v_8  [CC0805]  127.51 12.19 90 bottom
PC125  10u/25v_8  [CC0805]  129.54 12.19 90 bottom
PC126  0.1u/25v_4  [CC0402]  158.37 12.04 90 bottom
PC127  0.47u/25v_6  [CC0603]  142.88 11.94 180 bottom
PC128  100p/50v_4  [CC0402]  151.38 11.18 0 bottom
PC129  47n/50v_6  [CC0603]  142.54 10.67 0 bottom
PC130  2200p/50v_6  [CC0603]  136.91 7.49 270 bottom
PC131  4.7u/25v_8  [CC0805]  138.68 7.49 90 bottom
PC132  1u/16v_6  [CC0603]  143.26 6.22 0 bottom
PC133  0.01u/25v_4  [CC0402]  151.41 5.03 0 bottom
PC134  0.1u/25v_4  [CC0402]  144.65 3.94 180 bottom
PC135  0.1u/25v_4  [CC0402]  144.65 2.92 180 bottom
PC136  0.1u/25v_4  [CC0402]  146.94 2.79 0 bottom
PD1  1n4148ws  [DSM]  202.25 52.26 180 top
PD2  da2j10100l  [DSM]  163.32 54.23 0 bottom
PD3  sbr1045sp5-13  [POWER-6_5-1_84-3P]  183.39 50.8 0 bottom
PD4  smaj20a  [D-DO-214AC]  196.72 49.4 270 bottom
PD5  1ps302  [UMT_213-3-1_3]  53.21 46.99 270 bottom
PD6  1ps302  [UMT_213-3-1_3]  57.02 46.99 270 bottom
PD7  1ps302  [UMT_213-3-1_3]  60.96 46.99 270 bottom
PD8  rb500v-40  [DSM]  142.42 7.75 0 bottom
PJ1  dc-in  [1775295-4-4P-L]  202.65 60.58 270 bottom
PJ2  c114f3-108a1-l_batt_conn  [50458-00801-V02-8P-L]  109.1 7.76 172 bottom
PL1  0.15uh_7x7x4  [CHOKE-PCMC063T-R82MN-4P-SMT]  189.48 86.11 270 top
PL2  1uh_7x7x3  [CHOKE-PCMC063T-3R3MN-SMT]  182.09 73.43 180 top
PL3  2.2uh_7x7x3  [CHOKE-PCMC063T-3R3MN-SMT]  47.37 69.6 90 top
PL4  2.2uh_7x7x3  [CHOKE-PCMC063T-3R3MN-SMT]  55.25 69.6 90 top
PL5  2.2uh_7x7x3  [CHOKE-PCMC063T-3R3MN-SMT]  63.37 69.6 90 top
PL6  hcb2012vf-800t50  [RC0805]  196.34 55.5 90 bottom
PL7  hcb2012vf-800t50  [RC0805]  198.5 55.5 90 bottom
PL8  hcb2012vf-800t50  [RC0805]  106.17 18.16 180 bottom
PL9  hcb2012vf-800t50  [RC0805]  106.17 16 180 bottom
PL10  6.8uh_7x7x1.8  [CHOKE-PCMC063T-3R3MN-SMT]  125.35 6.98 0 bottom
PQ1  mdv1595s  [WDFN5-3_05X3_05-65]  190.63 74.42 0 top
PQ2  mdv1528  [WDFN5-3_05X3_05-65]  190.5 69.85 180 top
PQ3  dtc144eu  [UMT_213-3-1_3]  27.05 62.86 180 top
PQ4  mdv1528  [WDFN5-3_05X3_05-65]  61.9 62.61 90 top
PQ5  mdv1595s  [WDFN5-3_05X3_05-65]  66.47 62.43 270 top
PQ6  2n7002k  [SOT23_213-3_3-2]  34.42 61.21 180 top
PQ7  2n7002k  [SOT23_213-3_3-2]  26.92 58.17 180 top
PQ8  imd2at108  [IMD]  207.39 57.51 270 top
PQ9  2n7002k  [SOT23_213-3_3-2]  34.54 57.4 180 top
PQ10  2n7002k  [SOT23_213-3_3-2]  26.92 54.23 180 top
PQ11  2n7002k  [SOT23_213-3_3-2]  35.05 53.59 180 top
PQ12  ao3404  [SOT23_213-3_3-2]  26.92 50.42 180 top
PQ13  dtc144eu  [UMT_213-3-1_3]  35.18 50.29 180 top
PQ14  2n7002k  [SOT23_213-3_3-2]  134.62 15.62 0 top
PQ15  2n7002k  [SOT23_213-3_3-2]  150.72 13.61 270 top
PQ16  *2n7002k  [SOT23_213-3_3-2]  151.41 9.47 270 top
PQ17  2n7002k  [SOT23_213-3_3-2]  70.74 98.93 0 bottom
PQ18  2n7002k  [SOT23_213-3_3-2]  77.6 95.38 180 bottom
PQ19  2n7002k  [SOT23_213-3_3-2]  70.74 95.12 0 bottom
PQ20  dtc144eu  [UMT_213-3-1_3]  70.87 91.82 0 bottom
PQ21  2n7002k  [SOT23_213-3_3-2]  77.6 91.69 0 bottom
PQ22  *2n7002k  [SOT23_213-3_3-2]  77.92 88.08 180 bottom
PQ23  *pdtc143tt  [SOT23_213-3_3-2]  71.12 86.23 0 bottom
PQ24  *2n7002k  [SOT23_213-3_3-2]  77.6 84.33 180 bottom
PQ25  mdv1528q  [WDFN5-3_05X3_05-65]  60.07 81.53 0 bottom
PQ26  *mdv1528q  [WDFN5-3_05X3_05-65]  70.99 79.25 0 bottom
PQ27  ao3404  [SOT23_213-3_3-2]  60.45 77.09 0 bottom
PQ28  mdv1528q  [WDFN5-3_05X3_05-65]  70.99 74.68 0 bottom
PQ29  2n7002k  [SOT23_213-3_3-2]  159.89 67.82 270 bottom
PQ30  mdv1528q  [WDFN5-3_05X3_05-65]  41.78 67.44 270 bottom
PQ31  ao3404  [SOT23_213-3_3-2]  37.21 65.15 270 bottom
PQ32  2n7002k  [SOT23_213-3_3-2]  159.89 63.75 270 bottom
PQ33  dtc144eu  [UMT_213-3-1_3]  159 59.82 270 bottom
PQ34  ao3409  [SOT23_213-3_3-2]  158.62 55.88 270 bottom
PQ35  aol1413  [SO-8FL-5P-OA]  190.25 50.8 0 bottom
PQ36  aol1413  [SO-8FL-5P-OA]  125.86 17.27 0 bottom
PQ37  2n7002dw  [SC70-2_1-65-6P]  154.56 11.89 180 bottom
PQ38  mdv1528  [WDFN5-3_05X3_05-65]  133.73 10.16 180 bottom
PQ39  mdv1528  [WDFN5-3_05X3_05-65]  133.99 5.59 0 bottom
PR1  *short_8  [SHORT0805]  207.26 102.36 180 top
PR2  9.09k/f_4  [RC0402]  200.41 100.69 90 top
PR3  *39.2k/f_4  [RC0402]  201.52 100.25 90 top
PR4  39k/f_4  [RC0402]  202.56 100.25 270 top
PR5  2.2/f_6  [RC0603]  184.28 102.23 90 top
PR6  *0_4  [RC0402]  197.17 97.6 180 top
PR7  150k/f_4  [RC0402]  197.17 96.59 0 top
PR8  *56_4  [RC0402]  197.74 92.08 180 top
PR9  20/f_6  [RC0603]  199.9 91.69 90 top
PR10  2.2_6  [RC0603]  192.34 94.71 180 top
PR11  100k/f_4_4250ntc  [RC0402]  193.55 89.28 270 top
PR12  2.26k/f_4  [RC0402]  193.55 87.12 270 top
PR13  2.94k/f_4  [RC0402]  194.69 87.12 90 top
PR14  *short_4  [SHORT0402]  193.55 84.96 270 top
PR15  10k/f_4_3435ntc  [RC0402]  194.69 84.96 270 top
PR16  *4.7_6  [RC0603]  189.48 77.34 180 top
PR17  10k/f_4_3435ntc  [RC0402]  166.28 86.74 90 top
PR18  2/f_6  [RC0603]  193.68 65.41 270 top
PR19  10k/f_4  [RC0402]  199.01 63.98 0 top
PR20  1/f_6  [RC0603]  51.94 63.35 270 top
PR21  1/f_6  [RC0603]  42.29 62.94 0 top
PR22  *short_4  [SHORT0402]  49.5 62.64 0 top
PR23  *short_4  [SHORT0402]  188.72 62.48 0 top
PR24  20k/f_4  [RC0402]  199.01 62.23 180 top
PR25  *0_4  [RC0402]  190.37 61.72 90 top
PR26  *short_4  [SHORT0402]  49.5 61.59 0 top
PR27  *short_4  [SHORT0402]  188.72 61.47 0 top
PR28  60.4k/f_4  [RC0402]  191.9 60.96 180 top
PR29  1m_6  [RC0603]  26.92 60.71 0 top
PR30  1m_6  [RC0603]  30.23 60.71 0 top
PR31  10k/f_4  [RC0402]  58.67 60.71 0 top
PR32  *short_4  [SHORT0402]  42.29 60.56 180 top
PR33  220k_4  [RC0402]  206.25 60.58 270 top
PR34  *short_4  [SHORT0402]  207.39 60.58 90 top
PR35  *0_4  [RC0402]  51.69 60.45 180 top
PR36  *0_4  [RC0402]  188.72 60.33 180 top
PR37  *short_4  [SHORT0402]  50.16 59.94 90 top
PR38  1m_6  [RC0603]  38.23 59.82 0 top
PR39  12k/f_4  [RC0402]  191.9 59.82 180 top
PR40  *short_4  [SHORT0402]  58.67 59.56 0 top
PR41  *499k/f_4  [RC0402]  42.29 59.44 180 top
PR42  100k/f_4  [RC0402]  191.9 58.67 0 top
PR43  *short_6  [SHORT0603]  199.39 58.67 0 top
PR44  100k/f_4  [RC0402]  58.67 58.42 180 top
PR45  *499k/f_4  [RC0402]  51.69 58.39 0 top
PR46  22_8  [RC0805]  29.97 57.91 270 top
PR47  *1m_6  [RC0603]  39.37 57.78 270 top
PR48  1m_6  [RC0603]  31.75 57.53 90 top
PR49  220k_4  [RC0402]  205.04 57.34 270 top
PR50  22_8  [RC0805]  37.59 57.28 90 top
PR51  *short_6  [SHORT0603]  64.64 55.25 90 top
PR52  1m_6  [RC0603]  39.37 55.12 90 top
PR53  1m_6  [RC0603]  30.33 52.96 0 top
PR54  22_8  [RC0805]  38.73 52.07 270 top
PR55  *1m_6  [RC0603]  30.35 51.44 0 top
PR56  *100k/f_4  [RC0402]  64.47 47.07 90 top
PR57  69.8k/f_4  [RC0402]  65.53 47.07 270 top
PR58  *100k/f_4  [RC0402]  66.55 47.07 270 top
PR59  464k/f_4  [RC0402]  67.56 47.07 270 top
PR60  100k_4  [RC0402]  82.3 37.34 270 top
PR61  *short_4  [SHORT0402]  83.44 37.34 270 top
PR62  43.2k/f_4  [RC0402]  83.31 26.8 0 top
PR63  10k_4  [RC0402]  131.95 15.24 270 top
PR64  *100k_4  [RC0402]  153.29 14.48 90 top
PR65  *short_4  [SHORT0402]  105.16 12.06 90 top
PR66  100_4  [RC0402]  107.06 12.06 90 top
PR67  20_1206  [RC1206]  142.75 11.3 270 top
PR68  57.6k/f_4  [RC0402]  148.46 11.05 0 top
PR69  1m_4  [RC0402]  107.06 9.78 90 top
PR70  100_4  [RC0402]  109.09 9.78 90 top
PR71  100_4  [RC0402]  111 9.78 90 top
PR72  10k/f_4  [RC0402]  148.97 9.4 270 top
